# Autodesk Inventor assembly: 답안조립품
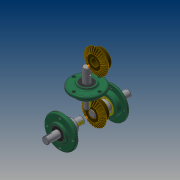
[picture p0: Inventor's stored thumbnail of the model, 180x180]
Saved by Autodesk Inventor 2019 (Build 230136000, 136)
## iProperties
Created: 2019-03
Part Number: 답안조립품
Material: 일반
Document SubType Name: Assembly
Designer: PC312-16
Author: PC312-16
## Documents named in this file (13)
- C:\Users\PC312-16\Desktop\490314V1004\답안조립품.iam
- C:\Users\PC312-16\Desktop\490314V1004\본체.ipt
- C:\Users\PC312-16\Desktop\490314V1004\커버.ipt
- C:\Users\PC312-16\Desktop\490314V1004\베어링 6203.ipt
- C:\Users\PC312-16\Desktop\490314V1004\오일 실.ipt
- 오일 실.ipt
- C:\Users\PC312-16\Desktop\490314V1004\메인 축.ipt
- 메인 축.ipt
- C:\Users\PC312-16\Desktop\490314V1004\서브 축.ipt
- 서브 축.ipt
- C:\Users\PC312-16\Desktop\490314V1004\키 5x5.ipt
- C:\Users\PC312-16\Desktop\490314V1004\키 4x4.ipt
- C:\Users\PC312-16\Desktop\490314V1004\메인 베벨기어.ipt
